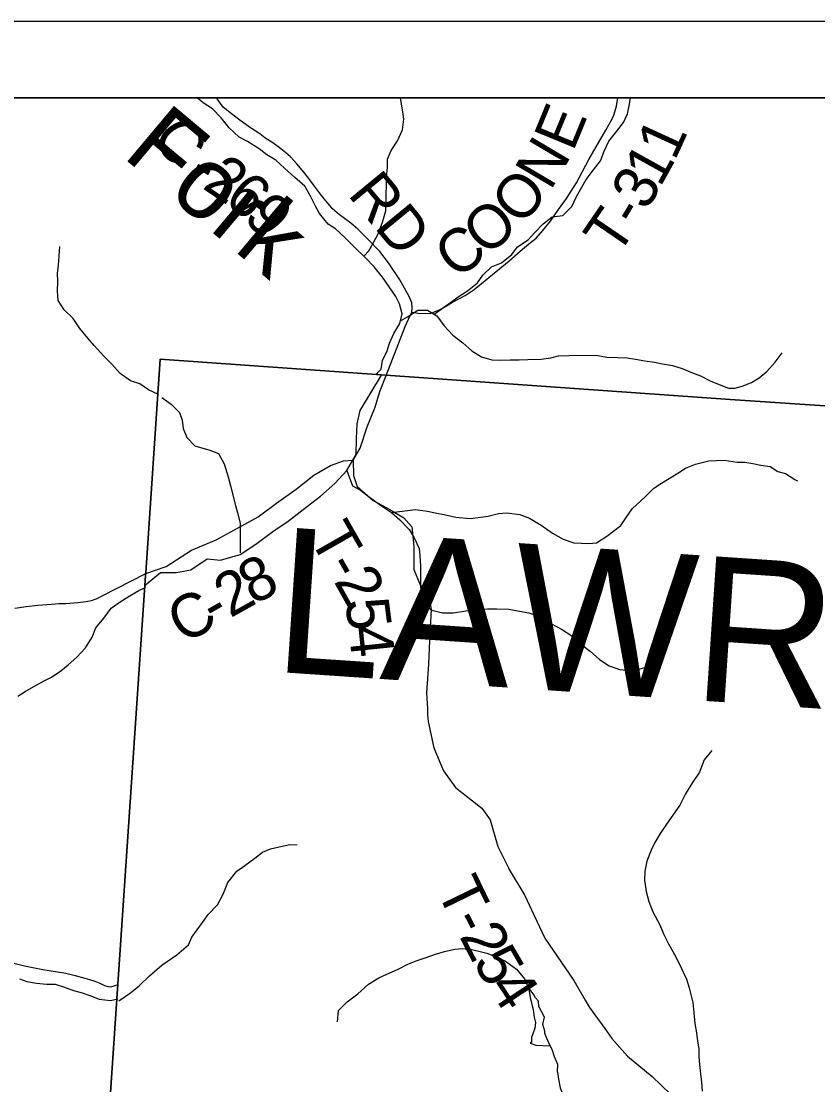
# Model space of a CAD drawing. Extents: x 0 to 82.7, y -0.2 to 22.
# Drawn here: x 2.703 to 3.743, y 19.61 to 21 of the extents above; entities that cross this region are included whole.
import ezdxf

# ---------------------------------------------------------------- set-up
doc = ezdxf.new("R2010")
doc.units = 0
for name, color, linetype in [('GM_X_County_Road', 7, 'Continuous'), ('GM_X_County_Road_Text', 7, 'Continuous'), ('GM_X_County_Text', 7, 'Continuous'), ('GM_X_Minor_Lake', 7, 'Continuous'), ('GM_X_Minor_River', 7, 'Continuous'), ('GM_X_Minor_River_Text', 7, 'Continuous'), ('GM_X_Township_Road', 7, 'Continuous'), ('GM_X_Township_Road_Text', 7, 'Continuous'), ('GM_X_Township_Text', 7, 'Continuous'), ('SH_Cut_Line', 7, 'Continuous'), ('SH_Data', 7, 'Continuous')]:
    doc.layers.add(name, color=color, linetype=linetype)

msp = doc.modelspace()

# ---------------------------------------------------------------- linework, layer by layer
at = {"layer": 'GM_X_County_Road'}
for points in [[(3.2085, 20.6106), (3.2129, 20.6197), (3.2133, 20.6253), (3.2127, 20.632), (3.2094, 20.6405), (3.1972, 20.6621), (3.1876, 20.6763), (3.1823, 20.6843), (3.1708, 20.6992), (3.1549, 20.7157), (3.1421, 20.7283), (3.1329, 20.736), (3.125, 20.7421), (3.1185, 20.7471), (3.1122, 20.7524), (3.1089, 20.7553), (3.1059, 20.7586), (3.1003, 20.7655), (3.0948, 20.7725), (3.0844, 20.7861), (3.0781, 20.7944), (3.0718, 20.803), (3.0624, 20.8139), (3.0544, 20.8227), (3.0483, 20.8279), (3.0418, 20.8334), (3.031, 20.8411), (3.0207, 20.8478), (3.0142, 20.8529), (3.0021, 20.8608), (2.9899, 20.8696), (2.9788, 20.8776), (2.9732, 20.8822), (2.9665, 20.8878), (2.9629, 20.8924), (2.9577, 20.9)], [(3.1793, 20.5369), (3.2039, 20.601), (3.2085, 20.6106)], [(2.8653, 20.2785), (2.8919, 20.2875), (2.9248, 20.309), (2.9571, 20.3224), (2.9857, 20.3378), (3.012, 20.3523), (3.036, 20.3703), (3.0615, 20.3883), (3.0848, 20.4068), (3.1065, 20.4195), (3.1236, 20.4254), (3.1362, 20.4264), (3.1454, 20.4423), (3.1543, 20.4699), (3.1648, 20.4957), (3.171, 20.5161), (3.1793, 20.5369)], [(2.6939, 20.2329), (2.7091, 20.235), (2.7242, 20.2367), (2.7422, 20.2381), (2.7517, 20.239), (2.7606, 20.239), (2.7764, 20.2402), (2.7875, 20.2417), (2.7944, 20.2431), (2.8015, 20.2457), (2.8082, 20.249), (2.8653, 20.2785)]]:
    msp.add_lwpolyline(points, dxfattribs=at)
at = {"layer": 'GM_X_Minor_Lake'}
for points in [[(3.3648, 19.7376), (3.3663, 19.7326), (3.3674, 19.7243), (3.3696, 19.7152), (3.3715, 19.7083), (3.3725, 19.6985), (3.3744, 19.6916), (3.3736, 19.6841), (3.3705, 19.6754), (3.369, 19.6723), (3.369, 19.6659), (3.3674, 19.6644), (3.375, 19.6617), (3.3935, 19.6608)], [(3.3935, 19.6608), (3.3887, 19.6719), (3.3868, 19.6772), (3.3865, 19.6802), (3.3839, 19.6889), (3.3862, 19.6984), (3.3787, 19.7125), (3.3783, 19.7193), (3.3742, 19.7239), (3.3716, 19.7284), (3.3667, 19.7349), (3.3648, 19.7376)]]:
    msp.add_lwpolyline(points, dxfattribs=at)
at = {"layer": 'GM_X_Minor_River'}
for points in [[(3.1661, 20.538), (3.1689, 20.5412), (3.1727, 20.5454), (3.1747, 20.5568), (3.1805, 20.5693), (3.1836, 20.5791), (3.1894, 20.592), (3.1971, 20.6052), (3.2002, 20.6177), (3.1969, 20.6306), (3.1917, 20.6401), (3.1834, 20.6531), (3.1744, 20.6657), (3.1636, 20.679), (3.1523, 20.6909), (3.1377, 20.7046), (3.1256, 20.7169), (3.1132, 20.7287), (3.1035, 20.7349), (3.0922, 20.7486), (3.087, 20.7585), (3.0803, 20.7715), (3.0732, 20.7844), (3.06, 20.7959), (3.0465, 20.8081), (3.0352, 20.8185), (3.0232, 20.8254), (3.0134, 20.8331), (2.9983, 20.843), (2.987, 20.8484), (2.9742, 20.8607), (2.9637, 20.8737), (2.9525, 20.8855), (2.94, 20.8932), (2.9323, 20.9)], [(3.1502, 20.6928), (3.1565, 20.6999), (3.1623, 20.7098), (3.1692, 20.723), (3.1746, 20.7373), (3.1789, 20.7521), (3.1794, 20.7623), (3.1795, 20.7745), (3.1799, 20.7851), (3.1796, 20.7965), (3.1809, 20.809), (3.181, 20.8196), (3.186, 20.8313), (3.194, 20.8438), (3.2006, 20.8581), (3.2022, 20.8722), (3.2011, 20.8817), (3.1993, 20.8915), (3.1981, 20.9)], [(3.2421, 20.6171), (3.251, 20.6237), (3.2635, 20.6323), (3.2734, 20.6398), (3.2856, 20.6477), (3.2985, 20.6582), (3.3058, 20.668), (3.3169, 20.6789), (3.3298, 20.6842), (3.3435, 20.6951), (3.3511, 20.7052), (3.3648, 20.7142), (3.3736, 20.724), (3.3843, 20.7353), (3.3961, 20.7443), (3.4101, 20.7461), (3.422, 20.7578), (3.4281, 20.771), (3.435, 20.7831), (3.4408, 20.7933), (3.4504, 20.8057), (3.4592, 20.8174), (3.4642, 20.8303), (3.4703, 20.8431), (3.4788, 20.8541), (3.4895, 20.8676), (3.4945, 20.879), (3.4972, 20.8915), (3.4985, 20.9)], [(2.8818, 20.5121), (2.8689, 20.5182), (2.8573, 20.5263), (2.8452, 20.5302), (2.8316, 20.5398), (2.8208, 20.552), (2.8106, 20.5623), (2.7979, 20.5761), (2.7896, 20.586), (2.7791, 20.5986), (2.7705, 20.6116), (2.7585, 20.623), (2.7506, 20.6352), (2.75, 20.6474), (2.7501, 20.6603), (2.7498, 20.6705), (2.751, 20.6811), (2.7519, 20.6933), (2.7527, 20.7058)], [(3.1978, 20.6083), (3.2073, 20.6138), (3.2207, 20.6224), (3.2332, 20.6223), (3.2456, 20.615), (3.2549, 20.6021), (3.2662, 20.5898), (3.2794, 20.5799), (3.291, 20.5692), (3.3038, 20.5615), (3.3174, 20.5576), (3.328, 20.5571), (3.3413, 20.5574), (3.353, 20.5577), (3.3644, 20.558), (3.3818, 20.5582), (3.3943, 20.56), (3.4045, 20.5626), (3.4178, 20.5632), (3.4322, 20.5635), (3.456, 20.5633), (3.4677, 20.5609), (3.4817, 20.5604), (3.4942, 20.56), (3.5052, 20.5584), (3.5173, 20.5564), (3.5301, 20.5544), (3.5403, 20.5524), (3.5536, 20.55), (3.566, 20.5461), (3.5796, 20.5407), (3.5902, 20.5365), (3.6034, 20.5295), (3.6265, 20.5207)], [(3.6265, 20.5207), (3.635, 20.5206), (3.6445, 20.5229), (3.6566, 20.5278), (3.6668, 20.5342), (3.6767, 20.5421), (3.6874, 20.5546), (3.6965, 20.5667)], [(2.865, 20.2636), (2.8846, 20.2797), (2.9051, 20.2796), (2.9241, 20.2832), (2.9454, 20.2975), (2.9628, 20.2959), (2.9886, 20.3033), (3.0092, 20.3168), (3.0313, 20.3333), (3.0511, 20.3469), (3.0709, 20.3619), (3.0937, 20.3792), (3.112, 20.3958), (3.128, 20.4131), (3.1403, 20.4336), (3.1404, 20.4548), (3.1413, 20.4738), (3.1452, 20.4913), (3.1731, 20.5374)], [(2.8861, 20.5084), (2.8984, 20.4998), (2.9091, 20.4889), (2.9126, 20.4786), (2.9139, 20.4676), (2.9189, 20.4559), (2.9293, 20.445), (2.949, 20.4395), (2.9601, 20.435), (2.9678, 20.4218), (2.9729, 20.4048), (2.9761, 20.393), (2.9824, 20.3673), (2.9852, 20.3574), (2.9887, 20.3442), (2.9886, 20.3051)], [(3.1863, 20.3582), (3.2178, 20.3619), (3.2334, 20.3598), (3.2433, 20.3576), (3.2569, 20.3551), (3.2703, 20.3518), (3.2889, 20.3501), (3.2995, 20.3513), (3.3127, 20.3534), (3.326, 20.3569), (3.3366, 20.3574), (3.3541, 20.3553), (3.3667, 20.3505), (3.3816, 20.3415), (3.3965, 20.331), (3.4106, 20.3232), (3.4243, 20.3184), (3.4437, 20.3174), (3.4543, 20.3183), (3.4675, 20.3271), (3.4859, 20.341), (3.4927, 20.3513), (3.5009, 20.3628), (3.5182, 20.3789), (3.5291, 20.39), (3.5389, 20.3962), (3.5604, 20.4093), (3.5702, 20.4158), (3.5835, 20.4213), (3.6009, 20.4256), (3.621, 20.4262)], [(3.621, 20.4262), (3.6377, 20.4236), (3.6479, 20.4239), (3.6585, 20.422), (3.6688, 20.42), (3.6809, 20.418), (3.691, 20.4115), (3.7012, 20.4088), (3.7133, 20.4011), (3.7167, 20.3992)], [(3.128, 20.4131), (3.1351, 20.3927), (3.1458, 20.3871), (3.1576, 20.3781), (3.1733, 20.3668), (3.1863, 20.3582), (3.197, 20.3485), (3.2093, 20.336), (3.2159, 20.3247), (3.2225, 20.3111), (3.2233, 20.3012), (3.2242, 20.2883), (3.2243, 20.2773), (3.224, 20.2671), (3.2246, 20.2515), (3.2273, 20.2394), (3.2388, 20.2304), (3.2529, 20.2271), (3.2673, 20.2269), (3.2832, 20.2293), (3.2931, 20.2301), (3.3117, 20.2322), (3.3238, 20.2323), (3.3394, 20.2317), (3.3534, 20.2292), (3.3656, 20.2267), (3.3778, 20.2226), (3.3954, 20.2125), (3.4083, 20.2054), (3.4206, 20.1976), (3.4351, 20.1852), (3.4458, 20.1769), (3.4581, 20.166), (3.4707, 20.1578), (3.4848, 20.153), (3.4977, 20.1516), (3.5094, 20.1532), (3.5234, 20.1572), (3.5397, 20.1615)], [(2.6981, 20.1179), (2.7076, 20.1239), (2.719, 20.1307), (2.7316, 20.1378), (2.7418, 20.143), (2.7544, 20.1512), (2.7639, 20.1588), (2.7753, 20.1689), (2.7864, 20.181), (2.7952, 20.1949), (2.7999, 20.2074), (2.8106, 20.2198), (2.8198, 20.233), (2.8319, 20.2413), (2.8437, 20.2488), (2.8559, 20.2559), (2.8648, 20.2602)], [(3.6046, 20.0471), (3.5949, 20.0348), (3.5886, 20.0188), (3.5796, 20.0051), (3.5706, 19.9902), (3.5628, 19.9757), (3.5456, 19.9505), (3.5374, 19.9386), (3.5303, 19.9268), (3.5254, 19.9168), (3.5199, 19.9024), (3.5174, 19.8891), (3.5167, 19.8777), (3.5188, 19.8629), (3.5227, 19.8496), (3.5278, 19.836), (3.5367, 19.819), (3.5417, 19.8073), (3.5483, 19.7944), (3.5579, 19.7774), (3.5653, 19.7619), (3.5719, 19.748), (3.575, 19.7366), (3.5798, 19.7177), (3.5814, 19.7044), (3.5827, 19.6904), (3.5847, 19.6778), (3.586, 19.6672), (3.588, 19.657), (3.5877, 19.6467), (3.5886, 19.6365), (3.5898, 19.6244), (3.5911, 19.6137), (3.5923, 19.6016)], [(2.8302, 19.72), (2.8452, 19.7304), (2.8565, 19.7392), (2.8701, 19.7526), (2.8863, 19.7665), (2.9059, 19.7799), (2.9209, 19.793), (2.9254, 19.8029), (2.9325, 19.8128), (2.9392, 19.8224), (2.9467, 19.8327), (2.9587, 19.8454), (2.9662, 19.8591), (2.9725, 19.8743), (2.9841, 19.8893), (2.9947, 19.8966), (3.0078, 19.9062), (3.0176, 19.9139), (3.0282, 19.9185), (3.0434, 19.9221), (3.0536, 19.9241), (3.0631, 19.9238)], [(3.1155, 19.6923), (3.1172, 19.7072), (3.1285, 19.7183), (3.1421, 19.729), (3.156, 19.7417), (3.1696, 19.7498), (3.1801, 19.7548), (3.1949, 19.7611), (3.2077, 19.7676), (3.2183, 19.7719), (3.2304, 19.7758), (3.2436, 19.7809), (3.2554, 19.7844), (3.269, 19.7872), (3.2785, 19.7884), (3.2906, 19.787), (3.3002, 19.7848), (3.3108, 19.7823), (3.323, 19.7775), (3.3352, 19.7715), (3.3494, 19.761), (3.3601, 19.7486), (3.3648, 19.7376)], [(2.7001, 19.7486), (2.7099, 19.7451), (2.7224, 19.7427), (2.7356, 19.7418), (2.747, 19.7417), (2.7576, 19.7382), (2.7708, 19.7332), (2.7821, 19.7301), (2.7919, 19.727), (2.8044, 19.7219), (2.8191, 19.7203), (2.8285, 19.7226)], [(3.4031, 19.6268), (3.4036, 19.6365), (3.3991, 19.6468), (3.3962, 19.6563), (3.3935, 19.6608)], [(3.4031, 19.6268), (3.4043, 19.6173), (3.4067, 19.6059), (3.4121, 19.5919), (3.4191, 19.5802), (3.4329, 19.569), (3.447, 19.5604), (3.4569, 19.5551), (3.4718, 19.5492), (3.4813, 19.5459), (3.492, 19.5418), (3.511, 19.5374), (3.5247, 19.5315), (3.538, 19.5274), (3.5494, 19.5241), (3.5597, 19.5208), (3.5723, 19.516), (3.5822, 19.5096), (3.5964, 19.501), (3.6369, 19.4821)]]:
    msp.add_lwpolyline(points, dxfattribs=at)
at = {"layer": 'GM_X_Township_Road'}
for points in [[(3.2605, 20.6296), (3.2658, 20.6327), (3.2824, 20.6416), (3.2942, 20.6496), (3.323, 20.673), (3.3402, 20.6869), (3.3544, 20.6994), (3.3656, 20.709), (3.3751, 20.7167), (3.3842, 20.7264), (3.394, 20.7389), (3.4046, 20.7538), (3.4147, 20.7682), (3.428, 20.7889), (3.4443, 20.8195), (3.4665, 20.8575), (3.474, 20.8715), (3.4766, 20.8773), (3.4804, 20.889), (3.4818, 20.9)], [(3.2129, 20.6197), (3.2212, 20.6185), (3.2307, 20.6179), (3.2381, 20.6185), (3.2497, 20.6234), (3.2605, 20.6296)], [(3.1362, 20.4264), (3.1367, 20.4063), (3.1415, 20.3922), (3.1622, 20.3738), (3.1841, 20.3619), (3.2022, 20.3511), (3.2127, 20.3393), (3.2155, 20.3142), (3.2153, 20.2834), (3.2238, 20.2636), (3.2347, 20.2506), (3.2379, 20.2313), (3.2362, 20.2009), (3.2347, 20.1599), (3.2321, 20.1224), (3.2332, 20.1013), (3.2335, 20.0937)], [(3.2335, 20.0937), (3.234, 20.0848), (3.2417, 20.0506), (3.2543, 20.0205), (3.27, 19.9984), (3.2858, 19.9861), (3.3043, 19.9715), (3.3151, 19.9562), (3.3254, 19.9215), (3.3334, 19.905), (3.3385, 19.8946)], [(3.3385, 19.8946), (3.34, 19.8916), (3.3604, 19.8573), (3.3692, 19.8387), (3.3867, 19.8018), (3.4246, 19.7464), (3.4395, 19.7209), (3.4451, 19.7113), (3.4648, 19.6837)], [(2.6811, 19.7723), (2.7069, 19.7655), (2.7305, 19.7607), (2.75, 19.7576), (2.7609, 19.7559), (2.7728, 19.7528), (2.7854, 19.7496), (2.7916, 19.7478), (2.7986, 19.7455), (2.8053, 19.7429), (2.8111, 19.74), (2.8159, 19.7385), (2.8197, 19.7383), (2.8237, 19.7392), (2.829, 19.741)], [(3.4648, 19.6837), (3.4743, 19.6705), (3.4944, 19.6474), (3.5268, 19.6209), (3.5502, 19.5982), (3.5586, 19.5562)]]:
    msp.add_lwpolyline(points, dxfattribs=at)
at = {"layer": 'GM_X_Township_Text'}
msp.add_lwpolyline([(6.1272, 20.9), (2.1, 20.9), (2.1, 19.5964), (2.2742, 19.1826), (2.3145, 19.0873), (2.397, 18.8926), (2.4438, 18.782), (2.7199, 18.1299), (2.7784, 18.9951), (2.7788, 19.0007), (2.8288, 19.7415), (2.8645, 20.2693), (2.8645, 20.2703), (2.8651, 20.279), (2.884, 20.5583), (3.179, 20.5374), (3.6288, 20.5056), (5.9672, 20.3493), (5.9756, 20.3782)], close=True, dxfattribs=at)
msp.add_lwpolyline([(5.9672, 20.3493), (3.6288, 20.5056), (3.179, 20.5374), (2.884, 20.5583), (2.8651, 20.279), (2.8645, 20.2703), (2.8645, 20.2693), (2.8288, 19.7415), (2.7788, 19.0007), (2.7784, 18.9951), (2.7199, 18.1299), (3.0279, 17.3486), (3.0556, 17.2782), (3.2909, 16.7562), (3.4071, 16.476), (3.6125, 15.9807), (3.8036, 15.5496), (4.1209, 14.8338)], dxfattribs=at)
at = {"layer": 'SH_Cut_Line'}
for points in [[(4.1209, 14.8338), (3.8036, 15.5496), (3.6125, 15.9807), (3.4071, 16.476), (3.2909, 16.7562), (3.0556, 17.2782), (3.0279, 17.3486), (2.7199, 18.1299), (2.7784, 18.9951), (2.7788, 19.0007), (2.8288, 19.7415), (2.8645, 20.2693), (2.8645, 20.2703), (2.8651, 20.279), (2.884, 20.5583), (3.179, 20.5374), (3.6288, 20.5056), (5.9672, 20.3493), (5.9756, 20.3782), (6.1272, 20.9), (2.1, 20.9), (2.1, 14.1)], [(8.9, 14.1), (8.9, 20.9), (6.1272, 20.9), (5.9756, 20.3782), (5.9672, 20.3493), (3.6288, 20.5056), (3.179, 20.5374), (2.884, 20.5583), (2.8651, 20.279), (2.8645, 20.2703), (2.8645, 20.2693), (2.8288, 19.7415), (2.7788, 19.0007), (2.7784, 18.9951), (2.7199, 18.1299), (3.0279, 17.3486), (3.0556, 17.2782), (3.2909, 16.7562), (3.4071, 16.476), (3.6125, 15.9807), (3.8036, 15.5496), (4.1209, 14.8338)]]:
    msp.add_lwpolyline(points, dxfattribs=at)
at = {"layer": 'SH_Data'}
for p, q in [((2, 21), (9, 21)), ((2.1, 20.9), (8.9, 20.9))]:
    msp.add_line(p, q, dxfattribs=at)

# ---------------------------------------------------------------- texts
at = {"layer": 'GM_X_County_Road_Text'}
for s, height, rotation, p in [('C', 0.0568, 305.4581, (2.8718, 20.8493)), ('2', 0.0568, 326.0184, (2.9377, 20.7825)), ('-', 0.0568, 329.8841, (2.9183, 20.7936)), ('6', 0.0568, 321.1407, (2.9656, 20.7637)), ('RD', 0.05682, 309.4283, (3.128, 20.7734)), ('9', 0.0568, 312.6111, (2.9913, 20.7432)), ('8', 0.0568, 27.9289, (3.0057, 20.2365)), ('2', 0.0568, 29.2517, (2.9755, 20.2196)), ('C', 0.0568, 29.6246, (2.9147, 20.1851)), ('-', 0.0568, 29.5546, (2.9553, 20.2081))]:
    msp.add_text(s, height=height, rotation=rotation, dxfattribs=at).set_placement(p)
at = {"layer": 'GM_X_County_Text'}
msp.add_text('LAWRENCE COUNTY', height=0.189394, rotation=356.1322, dxfattribs=at).set_placement((3.0295, 20.1501))
at = {"layer": 'GM_X_Minor_River_Text'}
msp.add_text('Fork', height=0.09471, rotation=319.9894, dxfattribs=at).set_placement((2.8332, 20.8236))
at = {"layer": 'GM_X_Township_Road_Text'}
for s, rotation, p in [('E', 67.6083, (3.4234, 20.8286)), ('1', 65.3861, (3.5563, 20.8167)), ('N', 59.3632, (3.394, 20.7776)), ('1', 61.0405, (3.5372, 20.7819)), ('3', 60.6469, (3.5199, 20.751)), ('O', 49.7716, (3.3556, 20.731)), ('O', 39.9379, (3.3098, 20.6914)), ('T', 55.6835, (3.4812, 20.6913)), ('-', 59.3194, (3.5072, 20.7297)), ('C', 38.0752, (3.2715, 20.6613)), ('T', 299.6311, (3.0777, 20.3254)), ('-', 299.6035, (3.0987, 20.2885)), ('2', 299.2634, (3.1102, 20.2683)), ('5', 277.4155, (3.1255, 20.2432)), ('4', 275.9118, (3.13, 20.2088)), ('T', 295.8962, (3.2442, 19.865)), ('-', 297.3992, (3.2634, 19.8253)), ('2', 297.627, (3.2743, 19.8043)), ('5', 300.2666, (3.2919, 19.7708)), ('4', 303.3891, (3.3113, 19.7377))]:
    msp.add_text(s, height=0.0568, rotation=rotation, dxfattribs=at).set_placement(p)

doc.saveas('drawing.dxf')
